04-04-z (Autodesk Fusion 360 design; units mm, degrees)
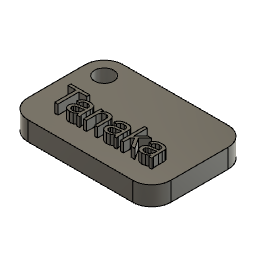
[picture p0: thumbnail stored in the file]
sketch "スケッチ1" plane through (0, 0, 0) normal (0, 1, 0) x axis (1, 0, 0)
  line L1 (-15, 10) -> (15, 10)
  line L2 (-15, -10) -> (-15, 10)
  line L3 (15, -10) -> (-15, -10)
  line L4 (15, 10) -> (15, -10)
  line L5 (-15, -10) -> (15, 10)
  line L6 (15, -10) -> (-15, 10)
  point P6 (0, 0)
  point P1 (0, 0)
  point P2 (15, 10)
  point P3 (-15, 10)
  point P5 (15, -10)
  horizontal L1
  perpendicular L1 L2
  parallel L1 L3
  parallel L2 L4
  coincident L5 P6
  coincident L6 P6
  coincident P1 P6
  dimension "d1" distance P2 P3 = 30
  dimension "d2" distance P2 P5 = 20
extrude "押し出し1" new body sketch "スケッチ1" profile of L1 L2 L3 L4 along normal blind 4
hole "穴" HoleDepth 4 HoleDiameter 4 TipAngle 118 RefDim1 4 RefDim2 4
sketch "スケッチ4" plane through (0, 4, 0) normal (0, 1, 0) x axis (-1, 0, 0)
  dimension "d17" = 5
  dimension "d22" = 4
  dimension "d23" = 11
extrude "押し出し3" add sketch "スケッチ4" along normal blind 2
fillet "フィレット" radius 4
